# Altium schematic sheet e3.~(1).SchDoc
size custom portrait; Address1: Address1; Address2: Address2; Address3: Address3; Address4: Address4; SheetNumber: 1; Scale: 1:1; Разраб.: Иванов; Обозначение документа: АБВГ.123456.001Э3; Пров.: Петров; Утв.: Сидоров; Наименование организации: ОАО "Ваша фирма"; Перв. применение: АБВГ.123456.000; Наименование изделия 1: Плата; Наименование изделия 2: Схема электрическая; Наименование изделия 3: принципиальная; Нач. отд.: Нач. отд.; Фамилия нач. отд.: Сидоров
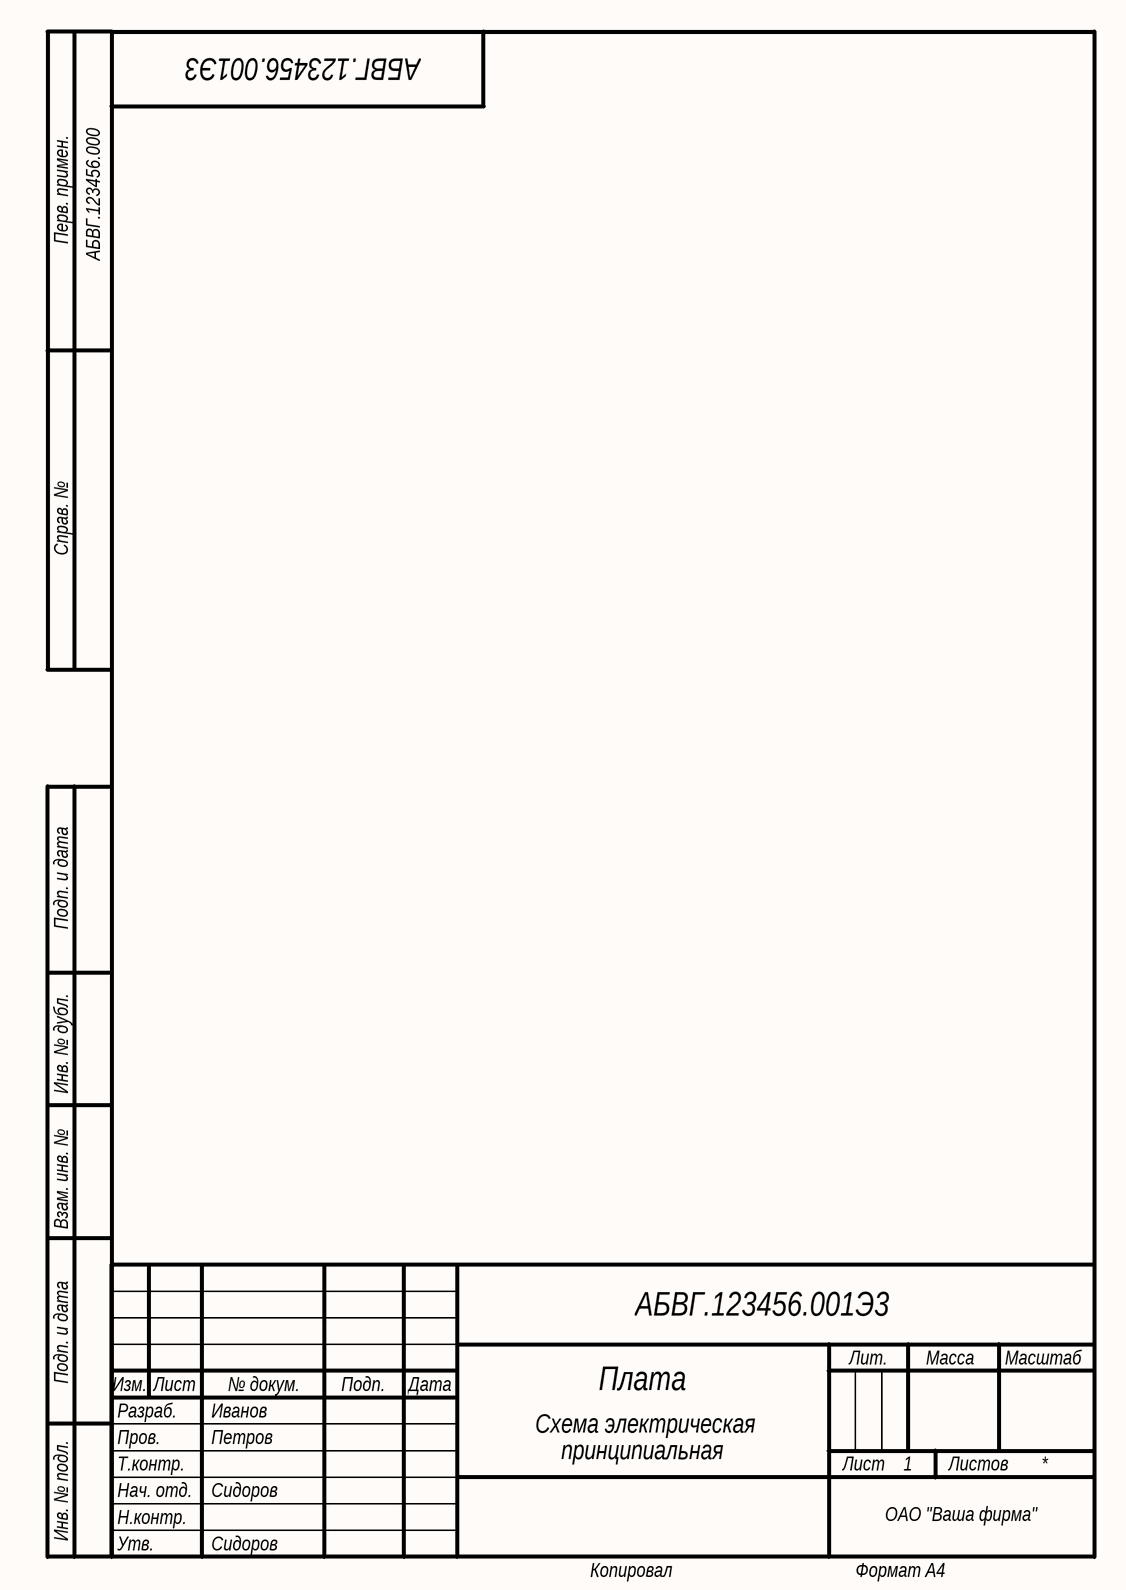
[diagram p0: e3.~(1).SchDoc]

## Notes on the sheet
- Перв. примен.
- Справ. №
- Подп. и дата
- Инв. № дубл.
- Взам. инв. №
- Разраб.
- Изм.
- Лист
- № докум.
- Подп.
- Дата
- Лит.
- Масса
- Масштаб
- Пров.
- Т.контр.
- Листов
- Инв. № подл.
- Утв.
- Н.контр.
- Копировал
- Формат А4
